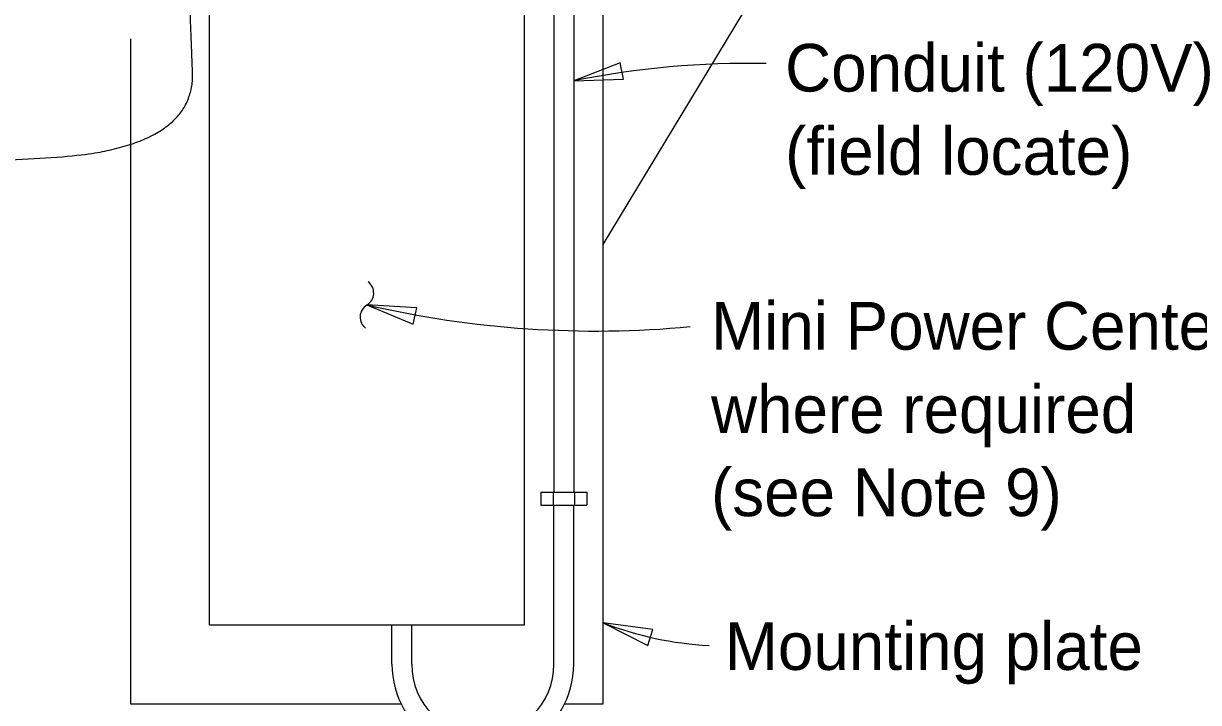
# Model space of a CAD drawing. Extents: x 112544 to 112597.1, y 111084 to 111107.1.
# Drawn here: x 112548.485 to 112552.213, y 111089.145 to 111091.298 of the extents above; entities that cross this region are included whole.
import ezdxf

# ---------------------------------------------------------------- set-up
doc = ezdxf.new("R2010")
doc.units = 0
for name, color, linetype in [('Dimension', 7, 'Continuous'), ('Lighting', 7, 'Continuous'), ('SteelGirder', 7, 'Continuous'), ('TextStructures', 7, 'Continuous')]:
    doc.layers.add(name, color=color, linetype=linetype)

msp = doc.modelspace()

# ---------------------------------------------------------------- linework, layer by layer
at = {"layer": 'Dimension'}
for points in [[(112550.2305, 111091.1162), (112550.3888, 111091.1213), (112550.3783, 111091.1732)], [(112549.5745, 111090.4058), (112549.7207, 111090.3448), (112549.7326, 111090.3963)], [(112550.3242, 111089.3973), (112550.4653, 111089.3253), (112550.4811, 111089.3758)]]:
    msp.add_lwpolyline(points, close=True, dxfattribs=at)
for centre, radius, start, end in [((112550.7823, 111088.3984), 2.7733, 88.7814, 101.4782), ((112549.5513, 111090.4435), 0.0447, 301.142, 52.8692), ((112549.5975, 111090.367), 0.0447, 121.142, 232.8692), ((112550.3005, 111093.5413), 3.2185, 256.9627, 275.3449), ((112550.7148, 111090.4055), 1.0813, 248.8193, 267.0903)]:
    msp.add_arc(centre, radius, start, end, dxfattribs=at)
msp.add_open_spline([(112546.6152, 111090.8361), (112548.0879, 111090.8463), (112549.0316, 111090.8974), (112549.0112, 111091.3926), (112548.9755, 111092.3627)], degree=2, dxfattribs=at)
at = {"layer": 'Lighting'}
for p, q in [((112550.1679, 111091.7197), (112550.1679, 111089.8121)), ((112550.2305, 111091.7197), (112550.2305, 111089.8121)), ((112550.1679, 111089.2659), (112550.1679, 111089.7704)), ((112550.2305, 111089.2659), (112550.2305, 111089.7704)), ((112549.654, 111089.2659), (112549.654, 111089.3909)), ((112549.7165, 111089.2659), (112549.7165, 111089.3909))]:
    msp.add_line(p, q, dxfattribs=at)
msp.add_lwpolyline([(112550.0742, 111092.1409), (112549.0742, 111092.1409), (112549.0742, 111089.3909), (112550.0742, 111089.3909)], close=True, dxfattribs=at)
for radius, start, end in [(0.2882, 179.9955, 0.0001), (0.2257, 180, 0)]:
    msp.add_arc((112549.9422, 111089.2659), radius, start, end, dxfattribs=at)
at = {"layer": 'SteelGirder'}
for p, q in [((112550.3242, 111090.5977), (112551.6978, 111092.8685)), ((112550.1259, 111089.8121), (112550.2725, 111089.8121)), ((112550.1259, 111089.8121), (112550.1259, 111089.7704)), ((112550.1653, 111089.8121), (112550.1653, 111089.7704)), ((112550.2331, 111089.8121), (112550.2331, 111089.7704)), ((112550.2725, 111089.8121), (112550.2725, 111089.7704)), ((112550.1259, 111089.7704), (112550.2725, 111089.7704))]:
    msp.add_line(p, q, dxfattribs=at)
for points in [[(112550.2018, 111089.1409), (112550.3242, 111089.1409), (112550.3242, 111092.3909), (112549.4361, 111092.3909)], [(112548.8242, 111091.2491), (112548.8242, 111089.1409), (112549.6826, 111089.1409)]]:
    msp.add_lwpolyline(points, dxfattribs=at)

# ---------------------------------------------------------------- texts
at = {"layer": 'Dimension'}
for s, p in [('Conduit (120V)', (112550.9012, 111091.0823)), ('(field locate)', (112550.9012, 111090.8183)), ('Mini Power Center', (112550.6663, 111090.2636)), ('where required', (112550.6663, 111089.9996)), ('(see Note 9)', (112550.6663, 111089.7356))]:
    msp.add_text(s, height=0.1512, dxfattribs=at).set_placement(p)
at = {"layer": 'TextStructures'}
msp.add_text('Mounting plate', height=0.1512, dxfattribs=at).set_placement((112550.7099, 111089.248))

doc.saveas('drawing.dxf')
